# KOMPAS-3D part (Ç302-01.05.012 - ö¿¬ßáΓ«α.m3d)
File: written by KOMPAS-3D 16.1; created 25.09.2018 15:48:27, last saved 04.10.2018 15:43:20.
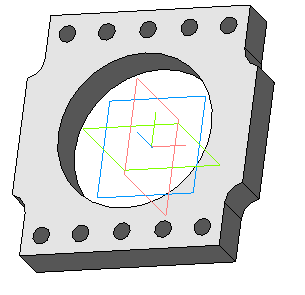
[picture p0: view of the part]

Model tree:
1. Эскиз:1
2. Операция выдавливания:1
     Расстояние 1 = 20
3. Скругление:1
     Радиус = 10
4. Эскиз:2
5. Вырезать элемент выдавливания:1
     Расстояние 1 = 20
6. Массив по сетке:1  (with: Вырезать элемент выдавливания:1, Эскиз:2)  (4 pattern instances)
     Угол раствора = -90; Шаг 2 = -2.15642; Номер 1 = 1
7. Эскиз:3
8. Вырезать элемент выдавливания:2
     Расстояние 1 = 20
9. Массив по сетке:2  (with: Вырезать элемент выдавливания:2, Эскиз:3)  (labels: А302-01.05.012)  (6 pattern instances)
     Угол раствора = -90; Номер 1 = 1

Expressions: v64*2; v81*2; v174*2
